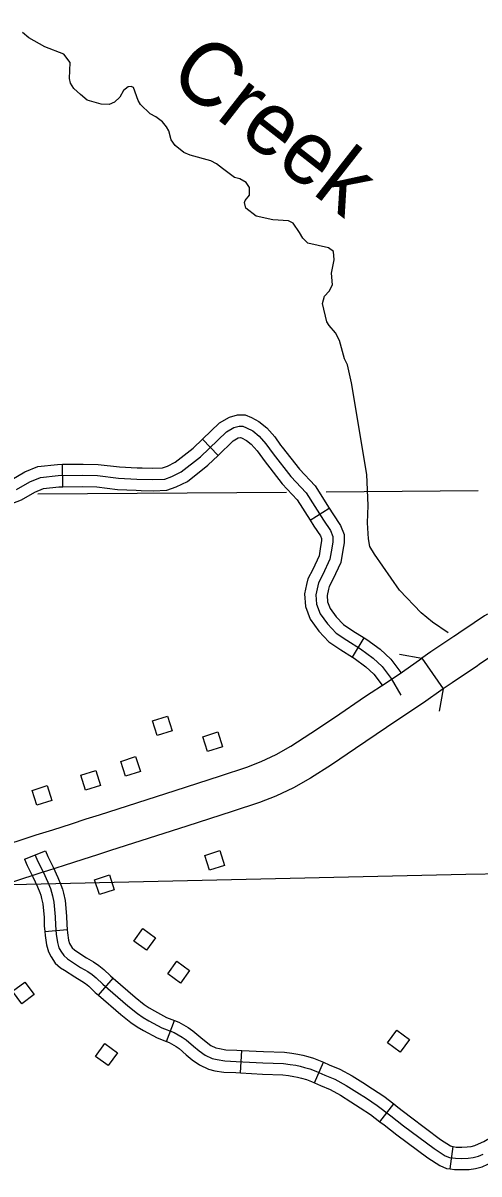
# Model space of a CAD drawing. Extents: x -19 to 366, y -4 to 359.
# Drawn here: x 128.531 to 129.107, y 199.218 to 200.67 of the extents above; entities that cross this region are included whole.
import ezdxf

# ---------------------------------------------------------------- set-up
doc = ezdxf.new("R2010")
doc.units = 0
for name, color, linetype in [('21', 7, 'Continuous'), ('R_Axis Annot', 7, 'Continuous'), ('R_Contour Annot', 7, 'Continuous'), ('R_ROW Annot', 7, 'Continuous'), ('R_Temp Easement', 7, 'Continuous'), ('R_Vert Alg', 7, 'Continuous'), ('Sheet Fence', 7, 'Continuous'), ('T_Indications', 7, 'Continuous')]:
    doc.layers.add(name, color=color, linetype=linetype)

msp = doc.modelspace()

# ---------------------------------------------------------------- linework, layer by layer
at = {"layer": '21'}
for points in [[(128.7009, 199.7713), (128.6949, 199.79), (128.7137, 199.796), (128.7197, 199.7773)], [(128.7644, 199.7511), (128.7584, 199.7699), (128.7772, 199.7759), (128.7832, 199.7571)], [(128.6607, 199.72), (128.6547, 199.7388), (128.6735, 199.7448), (128.6795, 199.726)], [(128.6103, 199.7025), (128.6044, 199.7213), (128.6232, 199.7273), (128.6292, 199.7085)], [(128.549, 199.6834), (128.5431, 199.7022), (128.5619, 199.7082), (128.5679, 199.6894)], [(128.7669, 199.6014), (128.761, 199.6202), (128.7798, 199.6262), (128.7858, 199.6074)], [(128.6278, 199.5707), (128.6218, 199.5895), (128.6406, 199.5955), (128.6466, 199.5767)], [(128.6988, 199.5164), (128.6872, 199.5005), (128.6712, 199.512), (128.6828, 199.528)], [(128.7415, 199.4751), (128.73, 199.4592), (128.714, 199.4707), (128.7255, 199.4867)], [(128.5456, 199.4446), (128.5297, 199.4329), (128.518, 199.4488), (128.5338, 199.4605)], [(129.0191, 199.3882), (129.0075, 199.3722), (128.9915, 199.3838), (129.0031, 199.3997)], [(128.6505, 199.3712), (128.639, 199.3552), (128.623, 199.3668), (128.6345, 199.3828)]]:
    msp.add_lwpolyline(points, close=True, dxfattribs=at)
at = {"layer": 'R_Axis Annot'}
for points in [[(128.55, 200.0761), (128.8638, 200.0784)], [(128.9139, 200.0788), (129.1058, 200.0803)]]:
    msp.add_lwpolyline(points, dxfattribs=at)
at = {"layer": 'R_Contour Annot'}
msp.add_line((129.0347, 199.8689), (129.0618, 199.8301), dxfattribs=at)
for points in [[(129.1175, 199.9246), (129.1141, 199.9223), (129.0877, 199.9047), (129.0845, 199.9025), (129.0814, 199.9005), (129.0784, 199.8984), (129.0753, 199.8963), (129.0463, 199.8771), (129.0347, 199.8689)], [(129.1442, 199.8855), (129.1405, 199.883), (129.1141, 199.8654), (129.111, 199.8633), (129.1078, 199.8612), (129.1046, 199.859), (129.1015, 199.8569), (129.073, 199.8379), (129.0618, 199.8301)], [(128.5393, 199.6433), (128.548, 199.6461), (128.569, 199.6526), (128.5924, 199.6601), (128.6113, 199.6662), (128.6278, 199.6714), (128.7236, 199.702), (128.7808, 199.7206), (128.8139, 199.7317), (128.8319, 199.7386), (128.8509, 199.7474), (128.8695, 199.7581), (128.8949, 199.7743), (128.9247, 199.7942), (128.9639, 199.8209), (128.9909, 199.8389), (129.0103, 199.8519), (129.0347, 199.8689)], [(129.0618, 199.8301), (129.037, 199.8128), (129.0172, 199.7996), (128.9904, 199.7816), (128.9512, 199.7549), (128.9207, 199.7346), (128.8941, 199.7177), (128.8728, 199.7053), (128.8504, 199.695), (128.8299, 199.6871), (128.7956, 199.6756), (128.7381, 199.6569), (128.642, 199.6262), (128.6256, 199.6211), (128.6069, 199.6151), (128.5833, 199.6075), (128.5623, 199.6009), (128.554, 199.5982)], [(128.5046, 199.6319), (128.5393, 199.6433)], [(128.554, 199.5982), (128.5192, 199.5869)]]:
    msp.add_lwpolyline(points, dxfattribs=at)
at = {"layer": 'R_ROW Annot'}
for p, q in [((128.5334, 199.6156), (128.5599, 199.6259)), ((128.5588, 199.5244), (128.5871, 199.5269)), ((128.6265, 199.444), (128.6451, 199.4655)), ((128.7126, 199.3854), (128.7228, 199.412)), ((128.8058, 199.3459), (128.8074, 199.3743)), ((128.8993, 199.3333), (128.9105, 199.3594)), ((128.982, 199.2843), (128.9993, 199.3069)), ((129.0704, 199.2248), (129.0744, 199.2529))]:
    msp.add_line(p, q, dxfattribs=at)
for points in [[(128.5466, 199.6207), (128.5496, 199.6132), (128.5567, 199.5993), (128.5625, 199.5865), (128.566, 199.5783), (128.5675, 199.5738), (128.5687, 199.5691), (128.5704, 199.5613), (128.5721, 199.5427), (128.5724, 199.5324), (128.5734, 199.5209), (128.575, 199.5103), (128.5767, 199.5038), (128.579, 199.4996), (128.5827, 199.494), (128.5876, 199.4898), (128.5915, 199.4871), (128.6041, 199.479), (128.6131, 199.4737), (128.6188, 199.47), (128.6238, 199.4659), (128.6321, 199.4579), (128.6639, 199.4304), (128.6759, 199.4208), (128.683, 199.4158), (128.6904, 199.4116), (128.7067, 199.4029), (128.7221, 199.397), (128.7323, 199.3911), (128.7372, 199.3878), (128.7465, 199.3797), (128.7536, 199.3738), (128.7612, 199.3682), (128.7703, 199.3641), (128.7765, 199.3627), (128.7861, 199.3611), (128.8006, 199.3604), (128.8342, 199.3585), (128.8603, 199.3578), (128.8685, 199.3567), (128.8758, 199.3555), (128.8814, 199.3545), (128.8869, 199.3528), (128.8936, 199.3509), (128.9009, 199.3481), (128.9125, 199.343), (128.9251, 199.3379), (128.9394, 199.33), (128.9527, 199.3216), (128.9648, 199.314), (128.9784, 199.305), (128.9958, 199.2916), (129.0117, 199.2792), (129.0504, 199.2504), (129.0644, 199.2415), (129.0697, 199.2392), (129.0771, 199.2382), (129.0854, 199.2381), (129.0932, 199.2383), (129.0997, 199.2392), (129.1063, 199.2408), (129.1123, 199.2436)], [(128.5599, 199.6259), (128.5625, 199.619), (128.5695, 199.6055), (128.5755, 199.5922), (128.5793, 199.5833), (128.5811, 199.5777), (128.5825, 199.5724), (128.5845, 199.5635), (128.5863, 199.5435), (128.5866, 199.5332), (128.5871, 199.5269)], [(128.5334, 199.6156), (128.5366, 199.6074), (128.5439, 199.5931), (128.5495, 199.5807), (128.5527, 199.5733), (128.5538, 199.5699), (128.5549, 199.5657), (128.5564, 199.5591), (128.5579, 199.5418), (128.5582, 199.5315), (128.5588, 199.5244)], [(128.5588, 199.5244), (128.5593, 199.5192), (128.5611, 199.5074), (128.5634, 199.4986), (128.5668, 199.4923), (128.5719, 199.4845), (128.5789, 199.4786), (128.5836, 199.4753), (128.5967, 199.4669), (128.6056, 199.4616), (128.6104, 199.4585), (128.6143, 199.4553), (128.6225, 199.4474), (128.6265, 199.444)], [(128.5871, 199.5269), (128.5875, 199.5226), (128.589, 199.5132), (128.59, 199.5091), (128.5912, 199.5068), (128.5934, 199.5035), (128.5962, 199.5011), (128.5994, 199.4989), (128.6116, 199.4911), (128.6205, 199.4858), (128.6272, 199.4815), (128.6332, 199.4765), (128.6417, 199.4684), (128.6451, 199.4655)], [(128.6451, 199.4655), (128.673, 199.4413), (128.6845, 199.4321), (128.6906, 199.4278), (128.6972, 199.4241), (128.7126, 199.4159), (128.7228, 199.412)], [(128.6265, 199.444), (128.6548, 199.4195), (128.6674, 199.4094), (128.6754, 199.4038), (128.6836, 199.3992), (128.7008, 199.39), (128.7126, 199.3854)], [(128.7228, 199.412), (128.7282, 199.4099), (128.7398, 199.4032), (128.7459, 199.3991), (128.7557, 199.3906), (128.7624, 199.385), (128.7685, 199.3805), (128.7749, 199.3776), (128.7792, 199.3766), (128.7876, 199.3752), (128.8013, 199.3746), (128.8074, 199.3743)], [(128.7126, 199.3854), (128.7159, 199.3842), (128.7247, 199.379), (128.7286, 199.3765), (128.7373, 199.3689), (128.7449, 199.3626), (128.754, 199.3559), (128.7657, 199.3506), (128.7737, 199.3487), (128.7847, 199.3469), (128.7999, 199.3463), (128.8058, 199.3459)], [(128.8074, 199.3743), (128.8349, 199.3727), (128.8614, 199.372), (128.8706, 199.3708), (128.8782, 199.3695), (128.8848, 199.3684), (128.8909, 199.3664), (128.8982, 199.3644), (128.9063, 199.3612), (128.9105, 199.3594)], [(128.9105, 199.3594), (128.918, 199.3561), (128.9312, 199.3507), (128.9467, 199.3422), (128.9603, 199.3336), (128.9725, 199.3259), (128.9867, 199.3166), (128.9993, 199.3069)], [(128.8058, 199.3459), (128.8336, 199.3443), (128.8592, 199.3436), (128.8665, 199.3427), (128.8734, 199.3415), (128.878, 199.3407), (128.8828, 199.3392), (128.8891, 199.3374), (128.8955, 199.3349), (128.8993, 199.3333)], [(128.8993, 199.3333), (128.907, 199.3299), (128.919, 199.3251), (128.9322, 199.3178), (128.9451, 199.3096), (128.9571, 199.302), (128.9702, 199.2934), (128.982, 199.2843)], [(128.9993, 199.3069), (129.0045, 199.3028), (129.0204, 199.2904), (129.0584, 199.2621), (129.071, 199.2541), (129.0736, 199.253), (129.0744, 199.2529)], [(128.982, 199.2843), (128.9871, 199.2804), (129.0031, 199.2679), (129.0423, 199.2387), (129.0577, 199.229), (129.0658, 199.2254), (129.0704, 199.2248)], [(129.0744, 199.2529), (129.0782, 199.2524), (129.0853, 199.2523), (129.092, 199.2525), (129.0971, 199.2532), (129.1016, 199.2543), (129.1064, 199.2565), (129.1131, 199.2596), (129.1225, 199.2648), (129.1361, 199.2758), (129.1441, 199.2828), (129.149, 199.2853), (129.154, 199.2874), (129.1569, 199.2885)], [(129.0704, 199.2248), (129.076, 199.224), (129.0856, 199.2239), (129.0944, 199.2241), (129.1024, 199.2252), (129.111, 199.2274), (129.1182, 199.2307), (129.1259, 199.2342), (129.1384, 199.2411), (129.1543, 199.254), (129.1602, 199.2591), (129.1611, 199.2596), (129.1645, 199.261), (129.1668, 199.2619)]]:
    msp.add_lwpolyline(points, dxfattribs=at)
at = {"layer": 'R_Temp Easement'}
for points in [[(128.931, 200.2695), (128.926, 200.2793), (128.9179, 200.2883), (128.9148, 200.2932), (128.9095, 200.3162), (128.912, 200.3254), (128.918, 200.3319), (128.922, 200.3399), (128.9207, 200.3543), (128.9242, 200.3714), (128.9233, 200.3817), (128.9168, 200.3865), (128.8909, 200.3922), (128.8844, 200.3986), (128.8805, 200.4057), (128.8724, 200.4174), (128.8667, 200.4203), (128.8469, 200.4216), (128.8257, 200.4266), (128.8127, 200.4366), (128.811, 200.4435), (128.8117, 200.4461), (128.8173, 200.453), (128.8172, 200.4625), (128.8129, 200.4689), (128.8049, 200.4733), (128.7984, 200.4751), (128.7831, 200.4863), (128.7758, 200.4923), (128.7686, 200.4963), (128.7424, 200.5032), (128.7344, 200.5065), (128.7233, 200.5154), (128.7186, 200.5226), (128.7154, 200.5339), (128.7127, 200.5392), (128.7073, 200.5452), (128.6992, 200.5515), (128.692, 200.5556), (128.6797, 200.5672), (128.6766, 200.5721), (128.6707, 200.5887), (128.668, 200.5898), (128.6642, 200.5897), (128.6582, 200.5847), (128.6538, 200.5763), (128.6467, 200.5701), (128.6403, 200.5674), (128.6301, 200.5676), (128.6122, 200.5727), (128.6038, 200.5798), (128.5957, 200.5876), (128.5915, 200.594), (128.5899, 200.6001), (128.5907, 200.6202), (128.583, 200.6307), (128.559, 200.6398), (128.5387, 200.6513), (128.5307, 200.658)], [(129.0682, 199.9009), (129.0481, 199.9145), (129.0339, 199.9261), (129.0066, 199.9549), (128.9749, 200), (128.9691, 200.0098), (128.9674, 200.0196), (128.9663, 200.0397), (128.9671, 200.0617), (128.9654, 200.1004), (128.9462, 200.2162), (128.941, 200.2389), (128.9374, 200.2464), (128.931, 200.2695)]]:
    msp.add_lwpolyline(points, dxfattribs=at)
at = {"layer": 'R_Vert Alg'}
for points in [[(129.0067, 199.8739), (129.0347, 199.8689)], [(129.0618, 199.8301), (129.0568, 199.8022)]]:
    msp.add_lwpolyline(points, dxfattribs=at)
at = {"layer": 'Sheet Fence'}
for points in [[(132.1027, 1.3746), (131.9232, 9.99), (131.7429, 18.6056), (131.5621, 27.2214), (131.3806, 35.8373), (131.1985, 44.4533), (131.0158, 53.0695), (130.8324, 61.6859), (130.6485, 70.3024), (130.4639, 78.919), (130.2786, 87.5358), (130.0928, 96.1527), (129.9063, 104.7698), (129.7193, 113.387), (129.5316, 122.0044), (129.3433, 130.6219), (129.1543, 139.2396), (128.9648, 147.8575), (128.7746, 156.4754), (128.5838, 165.0936), (128.3925, 173.7119), (128.2005, 182.3303), (128.0078, 190.9489), (127.8146, 199.5676), (127.6208, 208.1865), (127.4264, 216.8056), (127.2313, 225.4247), (127.0357, 234.0441), (126.8394, 242.6636), (126.6425, 251.2833), (126.4451, 259.9031), (126.247, 268.523), (126.0483, 277.1431), (125.849, 285.7634), (125.6492, 294.3838), (125.4487, 303.0044), (125.2476, 311.6252), (125.0459, 320.2461), (124.8437, 328.8671), (124.6408, 337.4883), (124.4373, 346.1097)], [(0, 198.1326), (7.1014, 198.137), (14.2028, 198.1503), (21.3042, 198.1724), (28.4055, 198.2034), (35.5068, 198.2433), (42.6081, 198.292), (49.7092, 198.3496), (56.8103, 198.4161), (63.9113, 198.4913), (71.0123, 198.5755), (78.1131, 198.6685), (85.2137, 198.7704), (92.3143, 198.8811), (99.4147, 199.0007), (106.5149, 199.1291), (113.615, 199.2664), (120.7149, 199.4126), (127.8146, 199.5676), (134.9141, 199.7315), (142.0135, 199.9042), (149.1125, 200.0858), (156.2114, 200.2762), (163.31, 200.4755), (170.4084, 200.6837), (177.5065, 200.9007), (184.6043, 201.1265), (191.7018, 201.3612), (198.799, 201.6048), (205.896, 201.8572), (212.9926, 202.1185), (220.0888, 202.3886), (227.1848, 202.6676), (234.2803, 202.9554), (241.3755, 203.2521), (248.4704, 203.5576), (255.5648, 203.872), (262.6589, 204.1952), (269.7525, 204.5273), (276.8457, 204.8682), (283.9385, 205.218), (291.0309, 205.5766), (298.1228, 205.9441), (305.2142, 206.3204), (312.3051, 206.7056), (319.3956, 207.0996), (326.4856, 207.5024), (333.5751, 207.9141), (340.664, 208.3347)], [(0, 189.5162), (7.1121, 189.5206), (14.2243, 189.5339), (21.3364, 189.556), (28.4484, 189.5869), (35.5605, 189.6267), (42.6725, 189.6754), (49.7844, 189.7329), (56.8962, 189.7992), (64.0079, 189.8744), (71.1196, 189.9584), (78.2311, 190.0512), (85.3425, 190.1529), (92.4538, 190.2635), (99.5649, 190.3829), (106.6759, 190.5111), (113.7867, 190.6482), (120.8974, 190.7941), (128.0078, 190.9489), (135.1181, 191.1125), (142.2282, 191.2849), (149.338, 191.4662), (156.4476, 191.6563), (163.5569, 191.8553), (170.666, 192.0631), (177.7749, 192.2798), (184.8835, 192.5053), (191.9917, 192.7396), (199.0997, 192.9828), (206.2074, 193.2348), (213.3147, 193.4956), (220.4218, 193.7653), (227.5285, 194.0438), (234.6348, 194.3312), (241.7408, 194.6274), (248.8464, 194.9324), (255.9516, 195.2463), (263.0564, 195.569), (270.1608, 195.9005), (277.2648, 196.2409), (284.3683, 196.5901), (291.4715, 196.9481), (298.5741, 197.315), (305.6763, 197.6907), (312.7781, 198.0753), (319.8793, 198.4686), (326.9801, 198.8708), (334.0804, 199.2818), (341.1801, 199.7017)]]:
    msp.add_spline(points, degree=3, dxfattribs=at)
at = {"layer": 'T_Indications'}
for p, q in [((128.7776, 200.1247), (128.758, 200.1452)), ((128.5816, 200.0851), (128.5812, 200.1135)), ((128.894, 200.0428), (128.918, 200.058)), ((128.9471, 199.8704), (128.9621, 199.8945))]:
    msp.add_line(p, q, dxfattribs=at)
for points in [[(128.758, 200.1452), (128.7796, 200.1659), (128.792, 200.1731), (128.8021, 200.1759), (128.8119, 200.1759), (128.8196, 200.1723), (128.8292, 200.1675), (128.8392, 200.1593), (128.8491, 200.1481), (128.8566, 200.1376)], [(128.5233, 200.0815), (128.5399, 200.0913), (128.5536, 200.0967), (128.5756, 200.0992), (128.607, 200.0996), (128.6254, 200.0992), (128.6518, 200.0959), (128.6749, 200.0949), (128.6954, 200.0941), (128.7102, 200.0949), (128.7193, 200.0981), (128.7312, 200.1039), (128.7553, 200.123), (128.7882, 200.1544), (128.7976, 200.1599), (128.8041, 200.1617), (128.8088, 200.1617), (128.8135, 200.1595), (128.8214, 200.1555), (128.8293, 200.149), (128.838, 200.1393), (128.847, 200.1266), (128.8694, 200.0981), (128.8889, 200.0775), (128.9105, 200.0432), (128.9196, 200.0299), (128.9224, 200.0223), (128.9224, 200.0158), (128.921, 200.0075), (128.9188, 199.9937), (128.9098, 199.9746), (128.9044, 199.9641), (128.9011, 199.9489), (128.9018, 199.937), (128.9065, 199.9247), (128.9156, 199.9121)], [(128.6817, 200.1088), (128.6953, 200.1084), (128.7074, 200.1089), (128.7137, 200.1112), (128.7236, 200.116), (128.746, 200.1338), (128.758, 200.1452)], [(128.7776, 200.1247), (128.7968, 200.143), (128.8031, 200.1467), (128.8058, 200.1474), (128.8073, 200.1467), (128.8136, 200.1435), (128.8195, 200.1388), (128.8269, 200.1304), (128.8335, 200.1211)], [(128.8566, 200.1376), (128.8584, 200.1352), (128.8802, 200.1074), (128.9002, 200.0863), (128.918, 200.058)], [(128.4832, 200.0828), (128.4985, 200.0874), (128.5171, 200.0944), (128.5336, 200.1041), (128.5501, 200.1106), (128.5747, 200.1134), (128.5812, 200.1135)], [(128.5812, 200.1135), (128.6071, 200.1138), (128.6264, 200.1134), (128.653, 200.1101), (128.6754, 200.1091), (128.6817, 200.1088)], [(128.6807, 200.0804), (128.6955, 200.0799), (128.713, 200.0808), (128.7248, 200.085), (128.7388, 200.0918), (128.7647, 200.1123), (128.7776, 200.1247)], [(128.8335, 200.1211), (128.8356, 200.1181), (128.8586, 200.0888), (128.8776, 200.0688), (128.894, 200.0428)], [(128.4914, 200.0556), (128.5076, 200.0604), (128.5294, 200.0686), (128.5461, 200.0784), (128.5571, 200.0828), (128.5765, 200.085), (128.5816, 200.0851)], [(128.5816, 200.0851), (128.6069, 200.0853), (128.6244, 200.085), (128.6506, 200.0818), (128.6743, 200.0807), (128.6807, 200.0804)], [(128.918, 200.058), (128.9224, 200.051), (128.9323, 200.0364), (128.9367, 200.0249), (128.9367, 200.0146), (128.935, 200.0051), (128.9326, 199.9895), (128.9226, 199.9683), (128.9179, 199.9593), (128.9171, 199.9558)], [(128.894, 200.0428), (128.8986, 200.0355), (128.9069, 200.0233), (128.9082, 200.0197), (128.9082, 200.017), (128.907, 200.0098), (128.9051, 199.998), (128.8971, 199.9809), (128.8909, 199.9689), (128.8893, 199.9618)], [(128.8893, 199.9618), (128.8868, 199.95), (128.8878, 199.934), (128.8939, 199.918), (128.9046, 199.903), (128.9176, 199.8896), (128.9324, 199.8796), (128.9471, 199.8704)], [(128.9171, 199.9558), (128.9154, 199.9479), (128.9159, 199.94), (128.9192, 199.9315), (128.9265, 199.9212), (128.9359, 199.9115), (128.9478, 199.9034), (128.9621, 199.8945)], [(128.9156, 199.9121), (128.9267, 199.9005), (128.9401, 199.8915), (128.9574, 199.8807), (128.9733, 199.8691), (128.9849, 199.8583), (128.996, 199.8435), (129.0083, 199.8221)], [(128.9621, 199.8945), (128.9654, 199.8925), (128.9824, 199.8801), (128.9955, 199.8678), (129.0084, 199.8507)], [(128.9471, 199.8704), (128.9495, 199.8689), (128.9642, 199.8582), (128.9743, 199.8488), (128.9848, 199.8348)]]:
    msp.add_lwpolyline(points, dxfattribs=at)

# ---------------------------------------------------------------- texts
at = {"layer": 'R_Temp Easement'}
msp.add_text('Creek', height=0.08, rotation=321.9868, dxfattribs=at).set_placement((128.7123, 200.5986))

doc.saveas('drawing.dxf')
